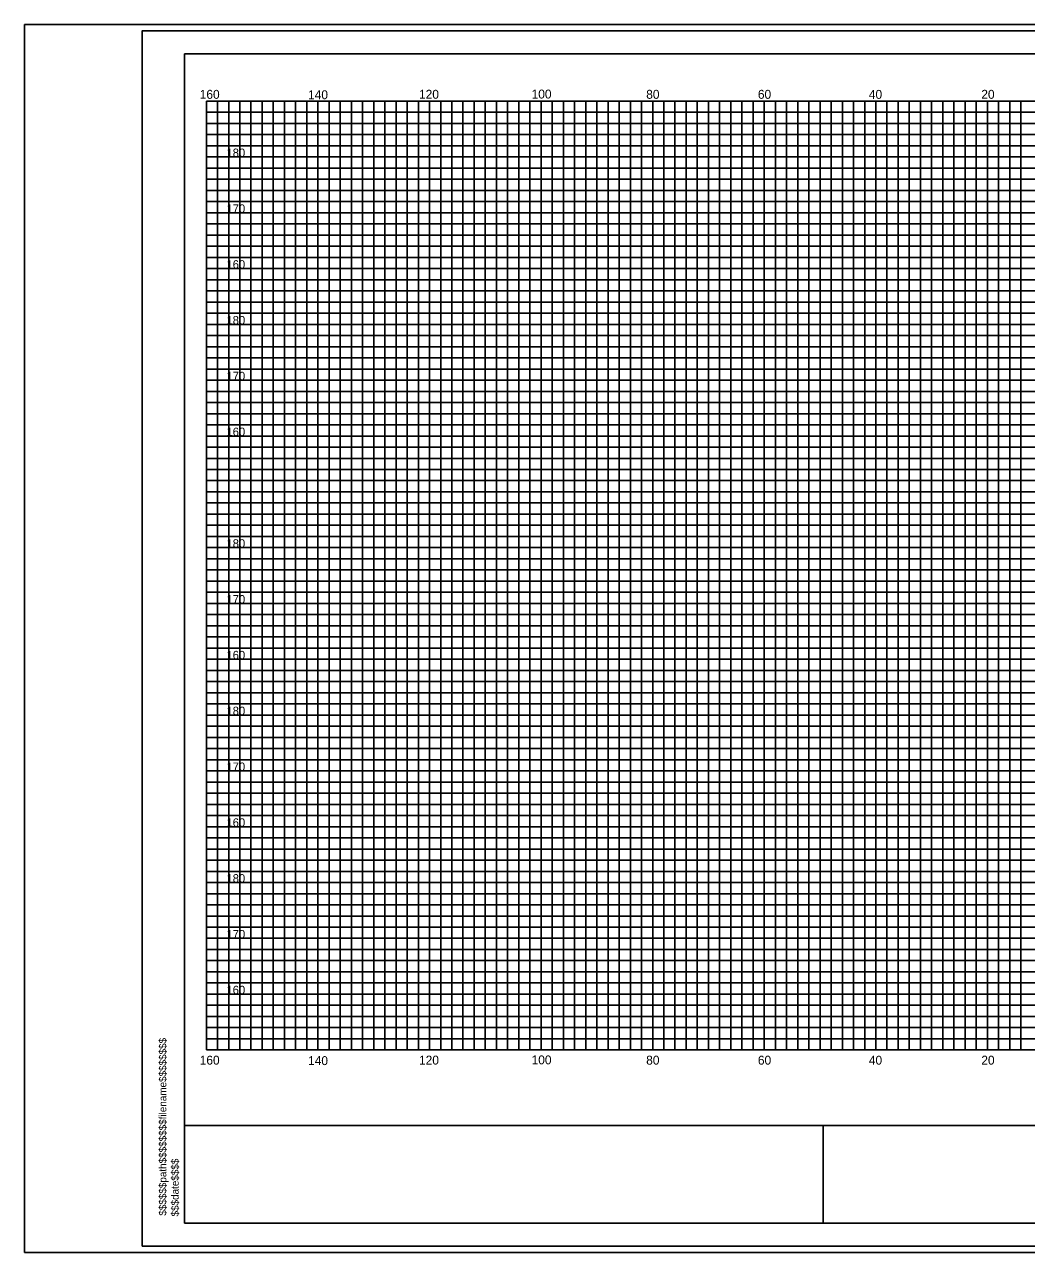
# Model space of a CAD drawing. Extents: x 967 to 1326, y 964 to 2864.
# Drawn here: x 967.4 to 1147, y 2083.7 to 2303.7 of the extents above; entities that cross this region are included whole.
import ezdxf

# ---------------------------------------------------------------- set-up
doc = ezdxf.new("R2010")
doc.units = 0
for name, color, linetype in [('Default', 7, 'Continuous'), ('RD_EX_RW', 7, 'Continuous'), ('RD_PD_Final_TX', 7, 'Continuous'), ('RD_SHT_ShtClip', 7, 'Continuous'), ('RD_XS_TX_Elev_PR', 7, 'Continuous'), ('RD_XS_TX_Slope', 7, 'Continuous')]:
    doc.layers.add(name, color=color, linetype=linetype)

msp = doc.modelspace()

# ---------------------------------------------------------------- linework, layer by layer
at = {"layer": 'RD_EX_RW'}
for p, q in [((1000, 2290), (1320, 2290)), ((1000, 2120), (1000, 2290)), ((1010, 2120), (1010, 2290)), ((1020, 2120), (1020, 2290)), ((1030, 2120), (1030, 2290)), ((1040, 2120), (1040, 2290)), ((1050, 2120), (1050, 2290)), ((1060, 2120), (1060, 2290)), ((1070, 2120), (1070, 2290)), ((1080, 2120), (1080, 2290)), ((1090, 2120), (1090, 2290)), ((1100, 2120), (1100, 2290)), ((1110, 2120), (1110, 2290)), ((1120, 2120), (1120, 2290)), ((1130, 2120), (1130, 2290)), ((1140, 2120), (1140, 2290)), ((1000, 2280), (1320, 2280)), ((1000, 2270), (1320, 2270)), ((1000, 2260), (1320, 2260)), ((1000, 2250), (1320, 2250)), ((1000, 2240), (1320, 2240)), ((1000, 2230), (1320, 2230)), ((1000, 2220), (1320, 2220)), ((1000, 2210), (1320, 2210)), ((1000, 2200), (1320, 2200)), ((1000, 2190), (1320, 2190)), ((1000, 2180), (1320, 2180)), ((1000, 2170), (1320, 2170)), ((1000, 2160), (1320, 2160)), ((1000, 2150), (1320, 2150)), ((1000, 2140), (1320, 2140)), ((1000, 2130), (1320, 2130)), ((1000, 2120), (1320, 2120))]:
    msp.add_line(p, q, dxfattribs=at)
at = {"layer": 'RD_PD_Final_TX'}
for p, q in [((996.11, 2088.98), (996.11, 2298.46)), ((996.11, 2298.46), (1323.89, 2298.46)), ((996.11, 2106.49), (1323.89, 2106.49)), ((1110.59, 2088.98), (1110.59, 2106.56)), ((1323.89, 2088.98), (996.11, 2088.98))]:
    msp.add_line(p, q, dxfattribs=at)
at = {"layer": 'RD_SHT_ShtClip'}
for p, q in [((1000, 2288), (1320, 2288)), ((1002, 2120), (1002, 2290)), ((1004, 2120), (1004, 2290)), ((1006, 2120), (1006, 2290)), ((1008, 2120), (1008, 2290)), ((1012, 2120), (1012, 2290)), ((1014, 2120), (1014, 2290)), ((1016, 2120), (1016, 2290)), ((1018, 2120), (1018, 2290)), ((1022, 2120), (1022, 2290)), ((1024, 2120), (1024, 2290)), ((1026, 2120), (1026, 2290)), ((1028, 2120), (1028, 2290)), ((1032, 2120), (1032, 2290)), ((1034, 2120), (1034, 2290)), ((1036, 2120), (1036, 2290)), ((1038, 2120), (1038, 2290)), ((1042, 2120), (1042, 2290)), ((1044, 2120), (1044, 2290)), ((1046, 2120), (1046, 2290)), ((1048, 2120), (1048, 2290)), ((1052, 2120), (1052, 2290)), ((1054, 2120), (1054, 2290)), ((1056, 2120), (1056, 2290)), ((1058, 2120), (1058, 2290)), ((1062, 2120), (1062, 2290)), ((1064, 2120), (1064, 2290)), ((1066, 2120), (1066, 2290)), ((1068, 2120), (1068, 2290)), ((1072, 2120), (1072, 2290)), ((1074, 2120), (1074, 2290)), ((1076, 2120), (1076, 2290)), ((1078, 2120), (1078, 2290)), ((1082, 2120), (1082, 2290)), ((1084, 2120), (1084, 2290)), ((1086, 2120), (1086, 2290)), ((1088, 2120), (1088, 2290)), ((1092, 2120), (1092, 2290)), ((1094, 2120), (1094, 2290)), ((1096, 2120), (1096, 2290)), ((1098, 2120), (1098, 2290)), ((1102, 2120), (1102, 2290)), ((1104, 2120), (1104, 2290)), ((1106, 2120), (1106, 2290)), ((1108, 2120), (1108, 2290)), ((1112, 2120), (1112, 2290)), ((1114, 2120), (1114, 2290)), ((1116, 2120), (1116, 2290)), ((1118, 2120), (1118, 2290)), ((1122, 2120), (1122, 2290)), ((1124, 2120), (1124, 2290)), ((1126, 2120), (1126, 2290)), ((1128, 2120), (1128, 2290)), ((1132, 2120), (1132, 2290)), ((1134, 2120), (1134, 2290)), ((1136, 2120), (1136, 2290)), ((1138, 2120), (1138, 2290)), ((1142, 2120), (1142, 2290)), ((1144, 2120), (1144, 2290)), ((1146, 2120), (1146, 2290)), ((1000, 2286), (1320, 2286)), ((1000, 2284), (1320, 2284)), ((1000, 2282), (1320, 2282)), ((1000, 2278), (1320, 2278)), ((1000, 2276), (1320, 2276)), ((1000, 2274), (1320, 2274)), ((1000, 2272), (1320, 2272)), ((1000, 2268), (1320, 2268)), ((1000, 2266), (1320, 2266)), ((1000, 2264), (1320, 2264)), ((1000, 2262), (1320, 2262)), ((1000, 2258), (1320, 2258)), ((1000, 2256), (1320, 2256)), ((1000, 2254), (1320, 2254)), ((1000, 2252), (1320, 2252)), ((1000, 2248), (1320, 2248)), ((1000, 2246), (1320, 2246)), ((1000, 2244), (1320, 2244)), ((1000, 2242), (1320, 2242)), ((1000, 2238), (1320, 2238)), ((1000, 2236), (1320, 2236)), ((1000, 2234), (1320, 2234)), ((1000, 2232), (1320, 2232)), ((1000, 2228), (1320, 2228)), ((1000, 2226), (1320, 2226)), ((1000, 2224), (1320, 2224)), ((1000, 2222), (1320, 2222)), ((1000, 2218), (1320, 2218)), ((1000, 2216), (1320, 2216)), ((1000, 2214), (1320, 2214)), ((1000, 2212), (1320, 2212)), ((1000, 2208), (1320, 2208)), ((1000, 2206), (1320, 2206)), ((1000, 2204), (1320, 2204)), ((1000, 2202), (1320, 2202)), ((1000, 2198), (1320, 2198)), ((1000, 2196), (1320, 2196)), ((1000, 2194), (1320, 2194)), ((1000, 2192), (1320, 2192)), ((1000, 2188), (1320, 2188)), ((1000, 2186), (1320, 2186)), ((1000, 2184), (1320, 2184)), ((1000, 2182), (1320, 2182)), ((1000, 2178), (1320, 2178)), ((1000, 2176), (1320, 2176)), ((1000, 2174), (1320, 2174)), ((1000, 2172), (1320, 2172)), ((1000, 2168), (1320, 2168)), ((1000, 2166), (1320, 2166)), ((1000, 2164), (1320, 2164)), ((1000, 2162), (1320, 2162)), ((1000, 2158), (1320, 2158)), ((1000, 2156), (1320, 2156)), ((1000, 2154), (1320, 2154)), ((1000, 2152), (1320, 2152)), ((1000, 2148), (1320, 2148)), ((1000, 2146), (1320, 2146)), ((1000, 2144), (1320, 2144)), ((1000, 2142), (1320, 2142)), ((1000, 2138), (1320, 2138)), ((1000, 2136), (1320, 2136)), ((1000, 2134), (1320, 2134)), ((1000, 2132), (1320, 2132)), ((1000, 2128), (1320, 2128)), ((1000, 2126), (1320, 2126)), ((1000, 2124), (1320, 2124)), ((1000, 2122), (1320, 2122))]:
    msp.add_line(p, q, dxfattribs=at)
at = {"layer": 'RD_XS_TX_Elev_PR'}
for points in [[(967.41, 2083.72), (1326.28, 2083.72), (1326.28, 2303.72), (967.41, 2303.72)], [(988.52, 2084.84), (1326.28, 2084.84), (1326.28, 2302.6), (988.52, 2302.6)]]:
    msp.add_lwpolyline(points, close=True, dxfattribs=at)

# ---------------------------------------------------------------- texts
at = {"layer": 'Default'}
for s, p in [('180', (1003.61, 2280)), ('170', (1003.61, 2270)), ('160', (1003.61, 2260)), ('180', (1003.61, 2250)), ('170', (1003.61, 2240)), ('160', (1003.61, 2230)), ('180', (1003.61, 2210)), ('170', (1003.61, 2200)), ('160', (1003.61, 2190)), ('180', (1003.61, 2180)), ('170', (1003.61, 2170)), ('160', (1003.61, 2160)), ('180', (1003.61, 2150)), ('170', (1003.61, 2140)), ('160', (1003.61, 2130))]:
    msp.add_text(s, height=1.5, dxfattribs=at).set_placement(p)
for s, p in [('$$$$$$path$$$$$$$$filename$$$$$$$$', (992.83, 2090.31)), ('$$$date$$$$', (995.04, 2090.17))]:
    msp.add_text(s, height=1.3258, rotation=90, dxfattribs=at).set_placement(p)
at = {"layer": 'RD_XS_TX_Slope'}
for s, p in [('160', (998.81, 2290.42)), ('140', (1018.23, 2290.34)), ('120', (1038.12, 2290.43)), ('100', (1058.3, 2290.47)), ('80', (1078.84, 2290.42)), ('60', (1098.86, 2290.42)), ('40', (1118.75, 2290.41)), ('20', (1138.91, 2290.42)), ('160', (998.81, 2117.37)), ('140', (1018.23, 2117.29)), ('120', (1038.12, 2117.38)), ('100', (1058.3, 2117.42)), ('80', (1078.84, 2117.37)), ('60', (1098.86, 2117.37)), ('40', (1118.75, 2117.36)), ('20', (1138.91, 2117.37))]:
    msp.add_text(s, height=1.6, dxfattribs=at).set_placement(p)

doc.saveas('drawing.dxf')
